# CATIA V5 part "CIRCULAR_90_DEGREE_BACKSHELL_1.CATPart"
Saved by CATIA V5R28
Part number: CIRCULAR_90_DEGREE_BACKSHELL_1
Revision: ---
Publications: "Logical Termination.1", "BaCP", "Face_generated(BackShellCnctPt1)", "Axis_generated(BackShellCnctPt1)", "Face_generated(BackShellCnctPt1).1", "BCP", "BCPRPoint_generated(BundleCnctPt1)", "BCPRPlane_generated(BundleCnctPt1)"
Bounding box of the stored display mesh (mm): x 0 to 42.443, y -18.288 to 18.288, z -33.528 to 17.367
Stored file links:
  C:\Users\ajc8720\Documents\BOEING_WORK\0001-2CES\004-AP242\Boeing-Generic_Harness_R3\CIRCULAR_90_DEGREE_BACKSHELL_1.CATPart
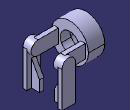
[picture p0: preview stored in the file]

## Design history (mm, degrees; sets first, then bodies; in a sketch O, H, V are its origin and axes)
Parameters
  PartNumber = "CIRCULAR_90_DEGREE_BACKSHELL_1"
Set1
  Set2 "EGF"
    Set3 "BCPOBody"
      Point1 "BCPRPoint": type Between, FirstPoint vertex [face of Pocket1 from Sketch5.L4 | start face of Pad3 | face of Pad3 from Sketch4.L2], SecondPoint vertex [face of Mirror1 | face of Mirror1 | face of Mirror1], Ratio 0.5
      Plane1 "BCPRPlane": type OffsetPt, RefPlane face of Mirror1, RefPoint Point1
    Set4 "BaCPOBody"
      Plane2 "BaCCPlane": type Offset, RefPlane yz-plane, Offset 7.62 {= deleted_LENGTH}
      Point2 "BaCPRPoint": type OnPlane, Support Plane2, H 0, V 0, Direction (0, 1, 0)
  Set5 "ConstructionGeometry"
    Plane3: type Offset, RefPlane zx-plane, Offset -10.4775 {= -( deleted_LENGTH / 2 )}
Body1 "PartBody" (main body)
  Sketch1 on yz-plane, origin (0, 0, 0), H (0, 1, 0), V (0, 0, 1)
    circle A1 centre (0, 0) radius 14.0589
    radius A1 = 14.0589
  Pad1: profile Sketch1, direction (1, 0, 0), length 1.4478 {= deleted_LENGTH}
  Sketch2 on end face of Pad1, origin (1.4478, 0, 0), H (0, 1, 0), V (0, 0, 1)
    circle A1 centre (0, 0) radius 17.4625
    radius A1 = 17.4625
  Pad2: profile Sketch2, direction (1, 0, 0), length 15.3162 {= deleted_LENGTH-deleted_LENGTH}
  Sketch3 on start face of Pad1, origin (0, 0, 0), H (0, 1, 0), V (0, 0, -1)
    point P1 (0, 0)
    coincidence: P1 O
  Hole1: placed by Sketch3, at (0, 0, 0) direction (1, 0, 0), diameter 17.9324 {= deleted_LENGTH}, depth 16.764 {= deleted_LENGTH}, counterbore diameter 25.4 {= deleted_LENGTH}, counterbore depth 7.62 {= deleted_LENGTH}
  Sketch4 on zx-plane, origin (0, 0, 0), H (1, 0, 0), V (0, 0, -1)
    line L1 (29.6926, 0) -> (29.6926, 33.528)
    line L2 (29.6926, 33.528) -> (42.4434, 33.528)
    line L3 (42.4434, 33.528) -> (42.4434, 0)
    arc A1 centre (36.068, 0) radius 6.3754 from (42.4434, 0) to (29.6926, 0) cw
    point P4 (36.068, 0)
    reference projected line E1 through (0, 0) direction (1, 0) from axis of face of Hole1
    angle L1 E1 = 90
    distance L3 L1 = 12.7508
    distance V P4 = 36.068
    distance P4 L2 = 33.528
    tangency: A1 L1, A1 L3
    coincidence: P4 H
    perpendicularity: L2 L1
  Pad3: profile Sketch4, direction (0, -1, 0), length 18.288 {= deleted_LENGTH/2}, opposite side length -6.985 {= -deleted_LENGTH/2}
  Sketch5 on start face of Pad3, origin (0, -6.985, 5.588), H (1, 0, 0), V (0, 0, -1)
    line L1 (29.6926, 39.116) -> (29.6926, 5.588)
    arc A1 centre (36.068, 5.588) radius 6.3754 from (29.6926, 5.588) to (42.4434, 5.588) ccw
    line L2 (42.4434, 5.588) -> (42.4434, 39.116)
    point P5 (42.4434, 39.116)
    line L3 (34.0106, 39.116) -> (29.6926, 39.116)
    line L4 (38.1254, 14.986) -> (38.1254, 39.116)
    line L5 (34.0106, 39.116) -> (34.0106, 14.986)
    line L6 (34.0106, 14.986) -> (38.1254, 14.986)
    reference projected line E1 (29.6926, 15.2) -> (29.6926, -12.232) from Sketch4.L1
    reference projected line E2 (123.9079, 39.116) -> (114.3575, 39.116) from Sketch4.L2
    reference projected line E3 (42.4434, -31.2456) -> (42.4434, -3.8136) from Sketch4.L3
    reference projected arc E4 centre (36.068, 5.588) radius 6.3754 from (36.068, 11.9634) to (36.068, -0.7874) ccw from Sketch4.A1
    line L7 (42.4434, 39.116) -> (38.1254, 39.116)
    distance L1 L5 = 4.318
    distance L4 L2 = 4.318
    distance L6 L7 = 24.13
    tangency: A1 L1, L2 A1
    coincidence: L1 E1, E2 L3, E3 L2, A1 E4, P5 L3
    parallelism: L6 L3
  Pocket1: profile Sketch5, direction (0, -1, 0), length 7.5565 {= deleted_LENGTH/2 - deleted_LENGTH/2 + deleted_LENGTH}
  Sketch6 on face of Pocket1 from Sketch5.L5, origin (34.0106, -3.6068, -36.6782), H (0, 0, -1), V (0, -1, 0)
    point P1 (-27.2802, 10.9347)
    line L1 (-27.2802, 10.9347) -> (-13.4372, 3.3782)
    point P2 (-13.4372, 3.3782)
    line L2 (-13.4372, 3.3782) -> (-27.2802, 3.3782)
    line L3 (-27.2802, 3.3782) -> (-27.2802, 10.9347)
    reference projected line E1 (-27.2802, 2.794) -> (-27.2802, 8.4836) from edge [face of Pocket1 from Sketch5.L6 | face of Pocket1 from Sketch5.L5]
    reference projected line E2 (42.6969, 3.3782) -> (58.928, 3.3782) from edge [start face of Pad3 | face of Pocket1 from Sketch5.L5]
    reference projected line E3 (58.928, 10.9347) -> (31.496, 10.9347) from edge [face of Pad3 from Sketch4.L1 | end face of Pocket1]
    reference projected line E4 (-3.1502, 2.794) -> (-3.1502, 8.4836) from edge [face of Pad3 from Sketch4.L2 | face of Pocket1 from Sketch5.L5]
    distance P2 E4 = 10.287 {= deleted_LENGTH}
    coincidence: L3 E1, L2 E2, P1 E3
  Pocket2: profile Sketch6, direction (1, 0, 0), through (limit type 6)
  Sketch7 on Plane3, origin (0, -10.4775, 9.7536), H (1, 0, 0), V (0, 0, 1)
    line L1 (16.764, -16.129) -> (36.068, -16.129)
    line L2 (36.068, -3.3782) -> (16.764, -3.3782)
    line L3 (16.764, -3.3782) -> (16.764, -16.129)
    arc A1 centre (36.068, -9.7536) radius 6.3754 from (36.068, -3.3782) to (36.068, -16.129) cw
    point P5 (36.068, -9.7536)
    reference intersected line E1 through (0, -9.7536) direction (-1, 0) from xy-plane
    distance V L3 = 16.764 {= deleted_LENGTH}
    distance L2 L1 = 12.7508 {= deleted_LENGTH}
    distance P5 V = 36.068 {= deleted_LENGTH + deleted_LENGTH}
    horizontal: L1 H, L2 H
    vertical: L3 V
    symmetry: L1 L2 E1
    tangency: A1 L2, A1 L1
  Pad4: profile Sketch7, direction (0, -1, 0), length 4.064 {= deleted_LENGTH}
  Mirror1: of Pad3, Sketch4, Pocket1, Sketch5, Pocket2, Sketch6, Pad4, Sketch7, about zx-plane
Body2 "BaCP"
  Sketch8 on Plane2, origin (7.62, 0, 0), H (0, 1, 0), V (0, 0, 1)
    arc A1 centre (0, 0) radius 1.016 from (-0.672, 0.762) to (0.672, 0.762) ccw
    line L1 (-0.672, 0.762) -> (0.672, 0.762)
    distance L1 H = 0.762
    radius A1 = 1.016
  Pad5: profile Sketch8, direction (1, 0, 0), length 0.508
